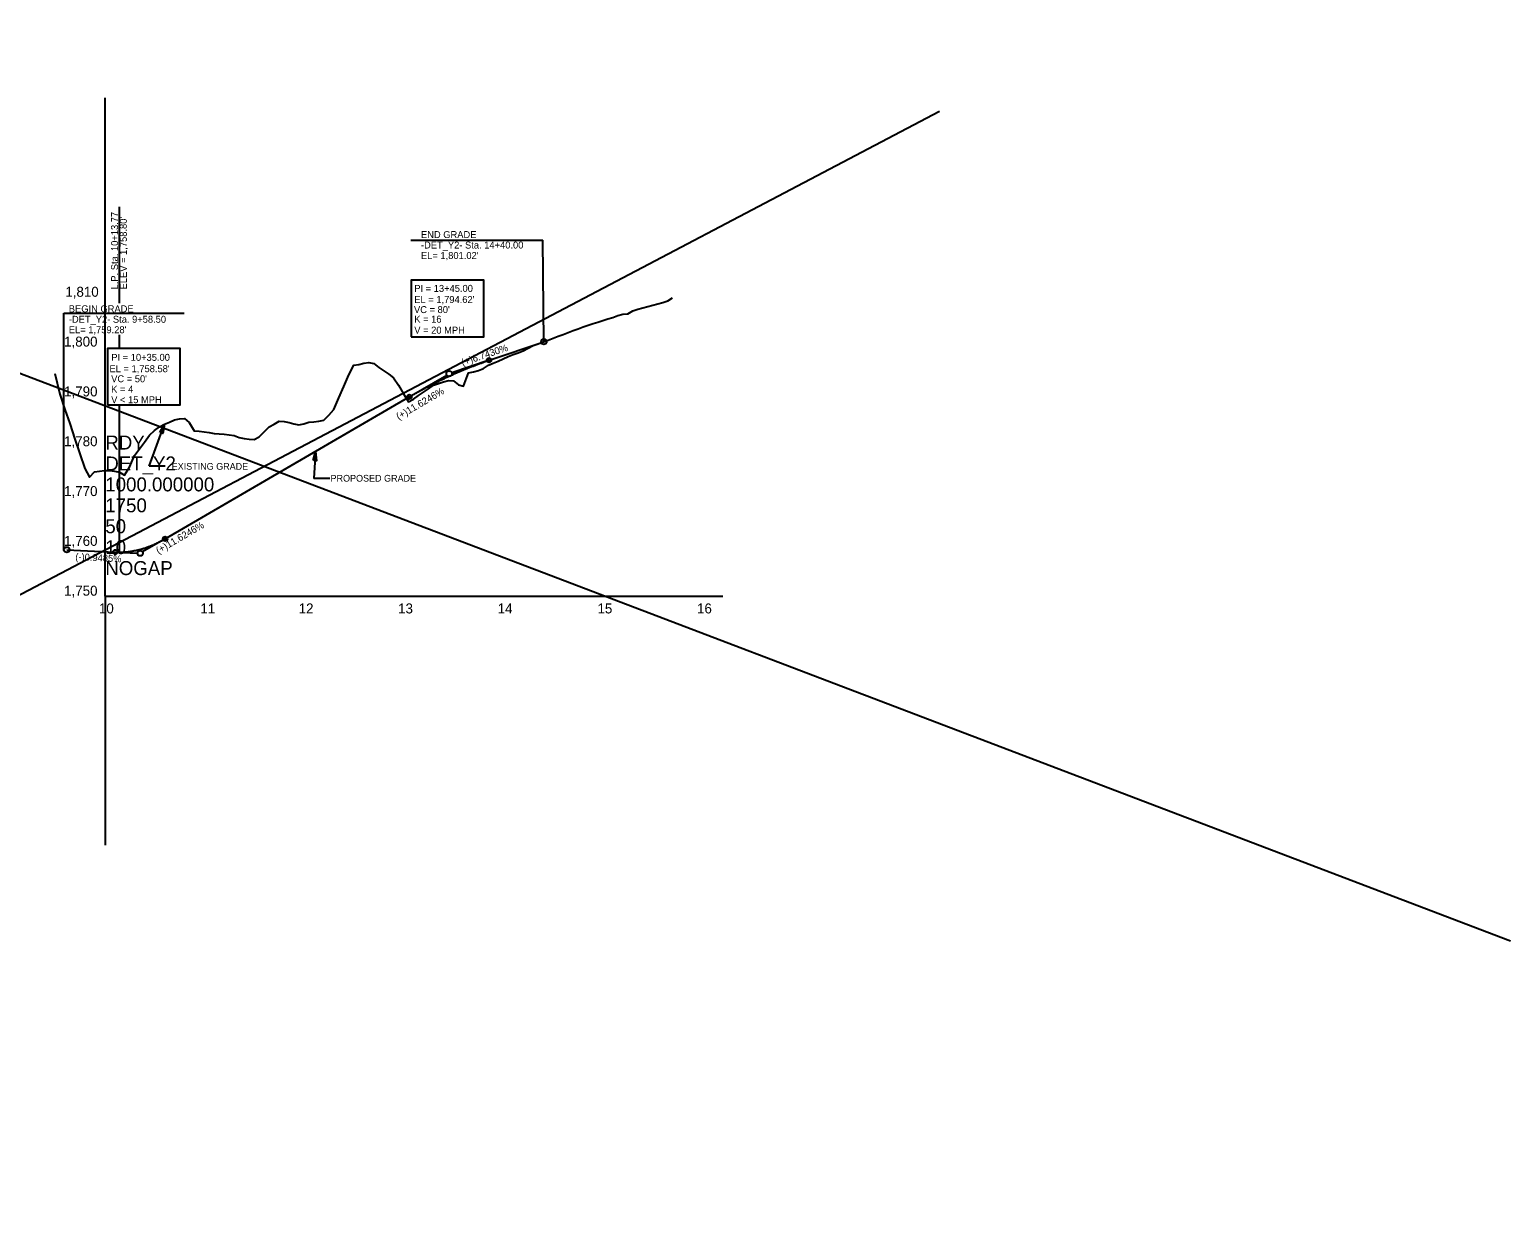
# Model space of a CAD drawing. Extents: x 498575 to 532350, y 405181 to 484585.
# Drawn here: x 505850 to 507336, y 475402 to 476603 of the extents above; entities that cross this region are included whole.
import ezdxf

# ---------------------------------------------------------------- set-up
doc = ezdxf.new("R2010")
doc.units = 0
for name, color, linetype in [('Exist Profile Cell', 7, 'Continuous'), ('Exist Vertical Profile Ground Line', 7, 'Continuous'), ('Exist Vertical Profile Horizontal Axis Label Major', 7, 'Continuous'), ('Exist Vertical Profile Vertical Axis Label', 7, 'Continuous'), ('Prop Grid Mask', 7, 'Continuous'), ('Prop PFL Text', 7, 'Continuous'), ('Prop Vertical Profile Curve Label', 7, 'Continuous'), ('Prop Vertical Profile Grade', 7, 'Continuous'), ('Prop Vertical Profile Grade Label', 7, 'Continuous'), ('Prop Vertical Profile Strip Grade', 7, 'Continuous'), ('Prop VPI Label', 7, 'Continuous'), ('Scratch_Level_5', 7, 'Continuous'), ('Typical Terminator CELL', 7, 'Continuous')]:
    doc.layers.add(name, color=color, linetype=linetype)

# ---------------------------------------------------------------- blocks, each defined once
blk = doc.blocks.new('TERMINATOR')
at = {"layer": 'Typical Terminator CELL'}
blk.add_lwpolyline([(-0.469, 0.081), (0, 0), (-0.471, -0.083), (-0.411, 0)], close=True, dxfattribs=at)

msp = doc.modelspace()

# ---------------------------------------------------------------- linework, layer by layer
at = {"layer": 'Exist Profile Cell'}
for q in [(505926.4, 476534.4), (506546, 476034.4), (505926.4, 475784.4)]:
    msp.add_line((505926.4, 476034.4), q, dxfattribs=at)
at = {"layer": 'Exist Vertical Profile Ground Line'}
for points in [[(506375.7, 476293.1), (506380.7, 476295.2), (506385.7, 476296.9), (506390.7, 476298.9), (506395.7, 476300.7), (506400.7, 476302.6), (506405.7, 476304.6), (506410.7, 476306.3), (506415.7, 476307.8), (506420.7, 476309.2), (506425.7, 476311), (506430.7, 476312.4), (506435.7, 476313.8), (506440.7, 476315.9), (506445.7, 476317.3), (506450.7, 476317.6), (506455.7, 476320.6), (506460.7, 476322.2), (506465.7, 476323.5), (506470.7, 476324.8), (506475.7, 476326.2), (506480.7, 476327.6), (506485.7, 476328.8), (506490.7, 476330.7), (506495.3, 476333.6)], [(505875.7, 476257.7), (505880.7, 476236.8), (505885.7, 476221.7), (505890.7, 476207.5), (505895.7, 476191.9), (505900.7, 476177.1), (505905.7, 476162.4), (505910.7, 476153.8), (505915.7, 476159), (505920.7, 476159.7), (505925.7, 476160.5), (505930.7, 476160.2), (505935.7, 476159.6), (505940.7, 476158.6), (505945.7, 476155.6), (505950.7, 476163.7), (505955.7, 476175.4), (505960.7, 476182.2), (505965.7, 476188.9), (505970.7, 476195.9), (505975.7, 476200.5), (505980.7, 476204.2), (505985.7, 476206.9), (505990.7, 476209), (505995.7, 476211.1), (506000.7, 476212.2), (506005.7, 476212.6), (506010.7, 476208.4), (506015.7, 476200.1), (506020.7, 476199.9), (506025.7, 476199.2), (506030.7, 476198.4), (506035.7, 476197.6), (506040.7, 476197.2), (506045.7, 476196.7), (506050.7, 476196.2), (506055.7, 476195.4), (506060.7, 476193.6), (506065.7, 476192.3), (506070.7, 476191.8), (506075.7, 476191.6), (506080.7, 476194.2), (506085.7, 476199.2), (506090.7, 476204.3), (506095.7, 476206.7), (506100.7, 476210), (506105.7, 476209.5), (506110.7, 476208.4), (506115.7, 476207.3), (506120.7, 476206.1), (506125.7, 476207.2), (506130.7, 476208.8), (506135.7, 476209.1), (506140.7, 476209.8), (506145.7, 476210.8), (506150.7, 476215.8), (506155.7, 476221.4), (506160.7, 476233.3), (506165.7, 476244.8), (506170.7, 476256.3), (506175.7, 476266.1), (506180.7, 476266.7), (506185.7, 476267.9), (506190.7, 476268.8), (506195.7, 476267.6), (506200.7, 476263.8), (506205.7, 476260.3), (506210.7, 476256.9), (506215.7, 476253.4), (506220.7, 476245.9), (506225.7, 476237.3), (506230.7, 476229.2), (506235.7, 476232), (506240.7, 476235.5), (506245.7, 476238.9), (506250.7, 476242.4), (506255.7, 476245.9), (506260.7, 476247.8), (506265.7, 476249.4), (506270.7, 476250.8), (506275.7, 476250.4), (506280.7, 476246.4), (506285.7, 476244.9), (506290.7, 476258.2), (506295.7, 476259.5), (506300.7, 476260.8), (506305.7, 476262.8), (506310.7, 476265.9), (506315.7, 476268), (506320.7, 476270.1), (506325.7, 476272.3), (506330.7, 476274.6), (506335.7, 476276.6), (506340.7, 476278.4), (506345.7, 476280.6), (506350.7, 476283.2), (506355.7, 476285.7), (506360.7, 476287.5), (506365.7, 476289.3), (506370.7, 476291.1), (506375.7, 476293.1)]]:
    msp.add_lwpolyline(points, dxfattribs=at)
at = {"layer": 'Prop Grid Mask'}
for points in [[(506233.2, 476294.6), (506306.2, 476294.6), (506306.2, 476351.4), (506233.2, 476351.4)], [(505928.6, 476226.1), (506001.6, 476226.1), (506001.6, 476282.9), (505928.6, 476282.9)]]:
    msp.add_lwpolyline(points, close=True, dxfattribs=at)
at = {"layer": 'Prop PFL Text'}
for p, q in [((505970.5, 476164.8), (505985.7, 476206.9)), ((506137.3, 476179.5), (506135.5, 476152.4)), ((505986.4, 476164.8), (505970.5, 476164.8)), ((506151.5, 476152.4), (506135.5, 476152.4))]:
    msp.add_line(p, q, dxfattribs=at)
at = {"layer": 'Prop Vertical Profile Curve Label'}
for centre in [(506311.4, 476271), (506231.4, 476234.2), (505986.4, 476091.8), (505936.4, 476078.5)]:
    msp.add_circle(centre, 2.25, dxfattribs=at)
at = {"layer": 'Prop Vertical Profile Grade'}
for p, q in [((506311.4, 476271), (506366.4, 476289.5)), ((505986.4, 476091.8), (506231.4, 476234.2)), ((505887.7, 476080.8), (505936.4, 476078.5))]:
    msp.add_line(p, q, dxfattribs=at)
for points in [[(506231.4, 476234.2), (506233, 476235.2), (506234.6, 476236.1), (506236.2, 476237), (506237.8, 476237.9), (506239.4, 476238.8), (506241, 476239.7), (506242.6, 476240.6), (506244.2, 476241.4), (506245.8, 476242.3), (506247.4, 476243.1), (506249, 476244), (506250.6, 476244.8), (506252.2, 476245.7), (506253.8, 476246.5), (506255.4, 476247.3), (506257, 476248.1), (506258.6, 476248.9), (506260.2, 476249.7), (506261.8, 476250.5), (506263.4, 476251.3), (506265, 476252), (506266.6, 476252.8), (506268.2, 476253.6), (506269.8, 476254.3), (506271.4, 476255), (506273, 476255.8), (506274.6, 476256.5), (506276.2, 476257.2), (506277.8, 476257.9), (506279.4, 476258.6), (506281, 476259.3), (506282.6, 476260), (506284.2, 476260.7), (506285.8, 476261.3), (506287.4, 476262), (506289, 476262.7), (506290.6, 476263.3), (506292.2, 476263.9), (506293.8, 476264.6), (506295.4, 476265.2), (506297, 476265.8), (506298.6, 476266.4), (506300.2, 476267), (506301.8, 476267.6), (506303.4, 476268.2), (506305, 476268.8), (506306.6, 476269.3), (506308.2, 476269.9), (506309.8, 476270.4), (506311.4, 476271)], [(505936.4, 476078.5), (505937.4, 476078.5), (505938.4, 476078.4), (505939.4, 476078.4), (505940.4, 476078.4), (505941.4, 476078.4), (505942.4, 476078.4), (505943.4, 476078.5), (505944.4, 476078.5), (505945.4, 476078.6), (505946.4, 476078.6), (505947.4, 476078.7), (505948.4, 476078.8), (505949.4, 476078.9), (505950.4, 476079.1), (505951.4, 476079.2), (505952.4, 476079.3), (505953.4, 476079.5), (505954.4, 476079.7), (505955.4, 476079.9), (505956.4, 476080.1), (505957.4, 476080.3), (505958.4, 476080.5), (505959.4, 476080.7), (505960.4, 476081), (505961.4, 476081.2), (505962.4, 476081.5), (505963.4, 476081.8), (505964.4, 476082.1), (505965.4, 476082.4), (505966.4, 476082.7), (505967.4, 476083.1), (505968.4, 476083.4), (505969.4, 476083.8), (505970.4, 476084.1), (505971.4, 476084.5), (505972.4, 476084.9), (505973.4, 476085.3), (505974.4, 476085.8), (505975.4, 476086.2), (505976.4, 476086.7), (505977.4, 476087.1), (505978.4, 476087.6), (505979.4, 476088.1), (505980.4, 476088.6), (505981.4, 476089.1), (505982.4, 476089.6), (505983.4, 476090.2), (505984.4, 476090.7), (505985.4, 476091.3), (505986.4, 476091.8)]]:
    msp.add_spline(points, degree=3, dxfattribs=at)
at = {"layer": 'Prop Vertical Profile Strip Grade'}
for p, q in [((505940.2, 476425), (505940.2, 476328.2)), ((505940.2, 476296.5), (505940.2, 476282.9)), ((505940.2, 476226.1), (505940.2, 476078.4))]:
    msp.add_line(p, q, dxfattribs=at)
at = {"layer": 'Prop VPI Label'}
for p, q in [((506232.9, 476391.6), (506365.4, 476391.6)), ((506366.4, 476289.5), (506365.4, 476391.6)), ((505884.9, 476080.8), (505884.9, 476318.1)), ((505884.9, 476318.1), (506005.4, 476318.1)), ((506311.4, 476271), (506274, 476258.4)), ((506231.4, 476234.2), (506269, 476256.1)), ((505986.4, 476091.8), (505963.8, 476078.7)), ((505936.4, 476078.5), (505958.7, 476077.4))]:
    msp.add_line(p, q, dxfattribs=at)
for centre in [(506366.4, 476289.5), (506271.4, 476257.5), (505887.7, 476080.8), (505961.4, 476077.3)]:
    msp.add_circle(centre, 2.75, dxfattribs=at)
at = {"layer": 'Scratch_Level_5'}
for p, q in [((504935.6, 476602.8), (507336.1, 475688.4)), ((504635.6, 475401.8), (506763.3, 476520.9))]:
    msp.add_line(p, q, dxfattribs=at)

# ---------------------------------------------------------------- block references
at = {"layer": 'Prop PFL Text'}
for p, xscale, yscale, rotation in [((505985.7, 476206.9), 19.999999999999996, 20, 70.13551694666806), ((506137.3, 476179.5), 20, 19.999999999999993, 86.29491613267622)]:
    msp.add_blockref('TERMINATOR', p, dxfattribs=dict(at, xscale=xscale, yscale=yscale, rotation=rotation))

# ---------------------------------------------------------------- texts
at = {"layer": 'Exist Profile Cell'}
for s, p in [('RDY', (505926.4, 476181.4)), ('DET_Y2', (505926.4, 476160.4)), ('1000.000000', (505926.4, 476139.4)), ('1750', (505926.4, 476118.4)), ('50', (505926.4, 476097.4)), ('10', (505926.4, 476076.4)), ('NOGAP', (505926.4, 476055.4))]:
    msp.add_text(s, height=14, dxfattribs=at).set_placement(p)
at = {"layer": 'Exist Vertical Profile Horizontal Axis Label Major'}
for s, p in [('10', (505920, 476016.9)), ('11', (506021.8, 476016.9)), ('12', (506120.4, 476016.9)), ('13', (506220.2, 476016.9)), ('14', (506320.1, 476016.9)), ('15', (506420.2, 476016.9)), ('16', (506520.1, 476016.9))]:
    msp.add_text(s, height=10, dxfattribs=at).set_placement(p)
at = {"layer": 'Exist Vertical Profile Vertical Axis Label'}
for s, p in [('1,810', (505886.3, 476334.7)), ('1,800', (505885.1, 476284.7)), ('1,790', (505885.1, 476234.7)), ('1,780', (505885.1, 476184.7)), ('1,770', (505885.1, 476134.7)), ('1,760', (505885.1, 476084.7)), ('1,750', (505885.1, 476034.7))]:
    msp.add_text(s, height=10, dxfattribs=at).set_placement(p)
at = {"layer": 'Prop PFL Text'}
for s, p in [('EXISTING GRADE', (505993, 476161.1)), ('PROPOSED GRADE', (506152.4, 476149.2))]:
    msp.add_text(s, height=6.75, dxfattribs=at).set_placement(p)
at = {"layer": 'Prop Vertical Profile Curve Label'}
for s, p in [("VC = 80'", (506236.1, 476318.3)), ('K = 16', (506236.4, 476308.7)), ('V = 20 MPH', (506236.4, 476297.7))]:
    msp.add_text(s, height=7, dxfattribs=at).set_placement(p)
at = {"layer": 'Prop Vertical Profile Grade Label'}
for s, rotation, p in [('(+)6.7430%', 18.6315, (506284.9, 476265.2)), ('(+)11.6246%', 30.1664, (506220.7, 476210.9)), ('(+)11.6246%', 30.1664, (505979.7, 476076.4)), ('(-)0.9485%', 357.2849, (505896.2, 476070.4))]:
    msp.add_text(s, height=7, rotation=rotation, dxfattribs=at).set_placement(p)
at = {"layer": 'Prop Vertical Profile Strip Grade'}
for s, p in [('L.P. Sta. 10+13.77', (505939.2, 476342.1)), ("ELEV = 1,758.80'", (505948, 476342.1))]:
    msp.add_text(s, height=7, rotation=90, dxfattribs=at).set_placement(p)
at = {"layer": 'Prop VPI Label'}
for s, p in [('END GRADE ', (506243.1, 476393.6)), ('-DET_Y2- Sta. 14+40.00', (506243.1, 476383.1)), ("EL= 1,801.02'", (506243.1, 476372.6)), ('PI = 13+45.00', (506236.4, 476339.6)), ('BEGIN GRADE', (505889.8, 476319.1)), ("EL = 1,794.62'", (506236.4, 476328.4)), ('-DET_Y2- Sta. 9+58.50', (505889.8, 476308.6)), ("EL= 1,759.28'", (505889.8, 476298.1)), ("EL = 1,758.58'", (505930.6, 476259)), ('PI = 10+35.00', (505932.4, 476270.4)), ("VC = 50'", (505932.3, 476248.9)), ('K = 4', (505932.3, 476238.4)), ('V < 15 MPH', (505932.3, 476227.9))]:
    msp.add_text(s, height=7, dxfattribs=at).set_placement(p)

doc.saveas('drawing.dxf')
